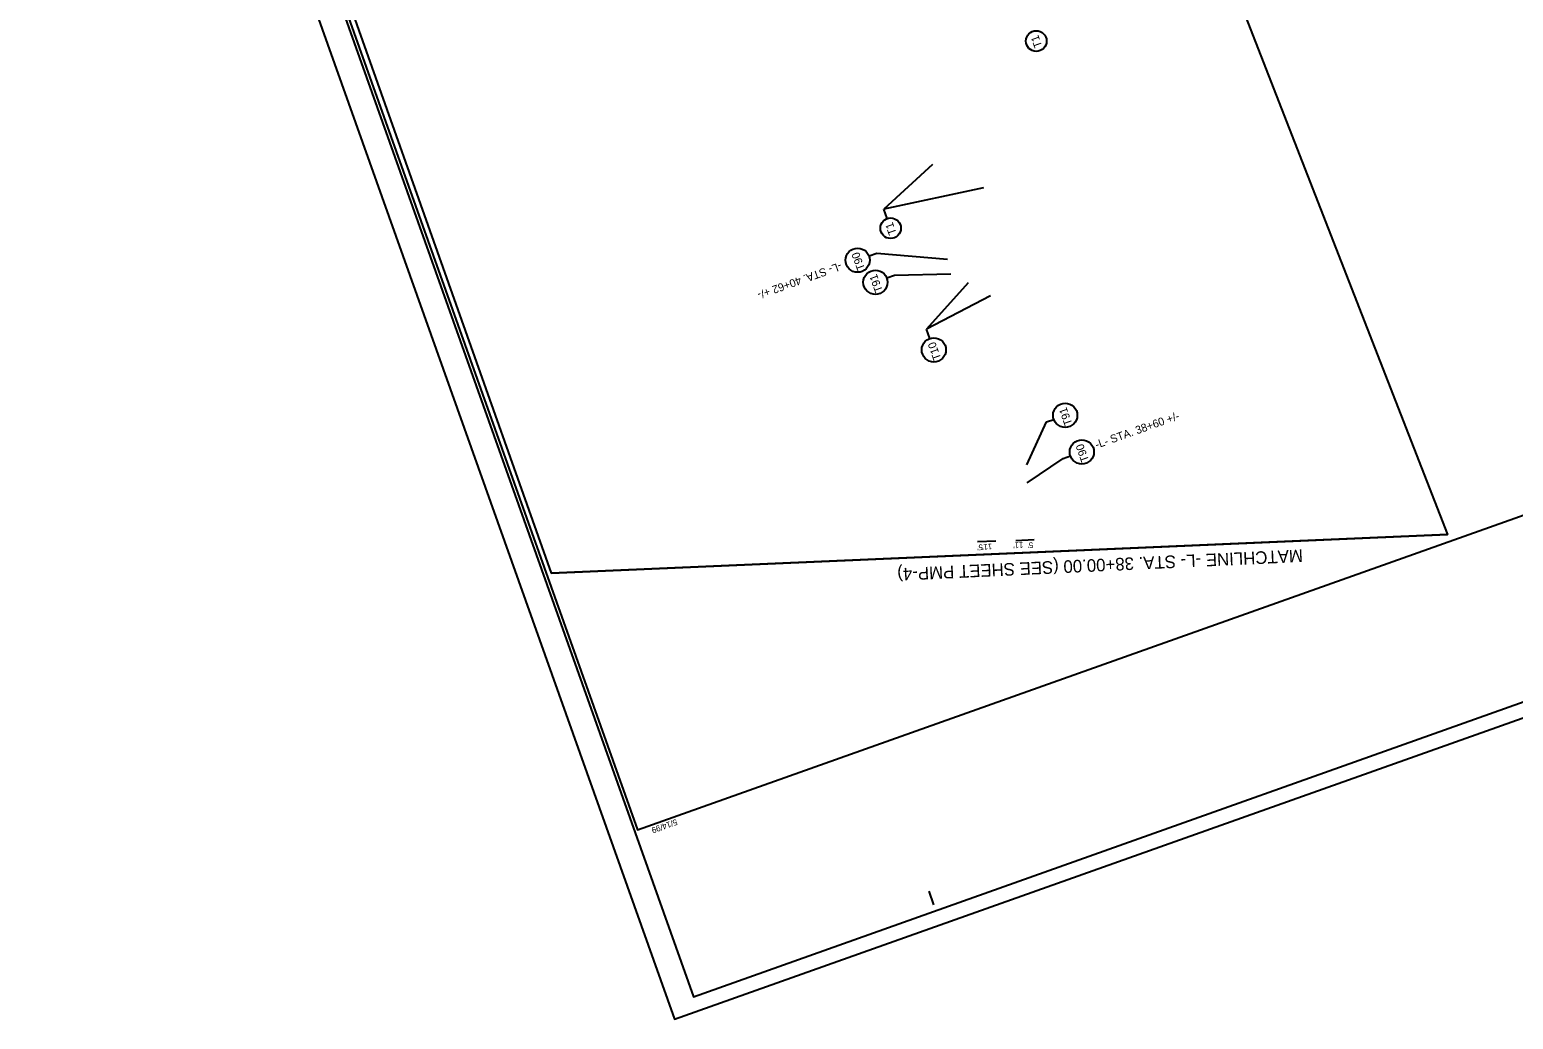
# Model space of a CAD drawing. Extents: x 1615843 to 1617934, y 901966 to 903921.
# Drawn here: x 1615843 to 1617141, y 901966 to 902832 of the extents above; entities that cross this region are included whole.
import ezdxf

# ---------------------------------------------------------------- set-up
doc = ezdxf.new("R2010")
doc.units = 0
for name, color, linetype in [('Matchline', 7, 'Continuous'), ('Matchline Text', 7, 'Continuous'), ('Sheet Border Standard 30in CELL', 7, 'Continuous'), ('Sheet Clip Boundary CELL', 7, 'Continuous'), ('Sheet Plot Border Inside CELL', 7, 'Continuous'), ('Sheet Plot Border Outside CELL', 7, 'Continuous'), ('Sheet Sticker Incomplete CELL', 7, 'Continuous')]:
    doc.layers.add(name, color=color, linetype=linetype)

msp = doc.modelspace()

# ---------------------------------------------------------------- linework, layer by layer
at = {"layer": 'Matchline'}
msp.add_line((1616299.5, 902356.1), (1617083.5, 902390), dxfattribs=at)
at = {"layer": 'Sheet Border Standard 30in CELL'}
for p, q in [((1616374.4, 902132.3), (1616374.4, 902132.3)), ((1616634.1, 902066), (1616629.9, 902077.8))]:
    msp.add_line(p, q, dxfattribs=at)
msp.add_lwpolyline([(1615872.3, 903544.7), (1616374.7, 902131.4), (1617364.1, 902483.1), (1616861.6, 903896.5)], close=True, dxfattribs=at)
at = {"layer": 'Sheet Clip Boundary CELL'}
for p, q in [((1616632.8, 902714), (1616590.3, 902674.8)), ((1616677.6, 902693.3), (1616590.3, 902674.8)), ((1616593.2, 902666.6), (1616590.3, 902674.8)), ((1616584.2, 902636.1), (1616577.4, 902633.6)), ((1616646.1, 902630.7), (1616584.2, 902636.1)), ((1616599.8, 902616.8), (1616593, 902614.4)), ((1616649.1, 902617.8), (1616599.8, 902616.8)), ((1616664.1, 902610.4), (1616627.7, 902569.7)), ((1616683.7, 902598.8), (1616627.7, 902569.7)), ((1616683.7, 902598.8), (1616627.7, 902569.7)), ((1616630.6, 902561.5), (1616627.7, 902569.7)), ((1616715.4, 902451.1), (1616732.8, 902488.6)), ((1616732.8, 902488.6), (1616739, 902490.8)), ((1616715.7, 902435.1), (1616747.3, 902456.5)), ((1616747.3, 902456.5), (1616753.6, 902458.8)), ((1616705.9, 902384.9), (1616721.9, 902385.5)), ((1616688.4, 902384.2), (1616672.4, 902383.5))]:
    msp.add_line(p, q, dxfattribs=at)
for centre, radius in [((1616723.7, 902821.9), 9.01), ((1616596.3, 902658.1), 9.01), ((1616567.4, 902630.1), 10.6), ((1616583, 902610.8), 10.6), ((1616634.1, 902551.6), 10.6), ((1616749, 902494.4), 10.6), ((1616763.6, 902462.3), 10.6)]:
    msp.add_circle(centre, radius, dxfattribs=at)
at = {"layer": 'Sheet Plot Border Inside CELL'}
msp.add_lwpolyline([(1615865.7, 903555.7), (1616423.9, 901985.4), (1617418.1, 902338.9), (1616859.8, 903909.1)], close=True, dxfattribs=at)
at = {"layer": 'Sheet Plot Border Outside CELL'}
msp.add_lwpolyline([(1615843, 903552.4), (1616407.1, 901965.7), (1617443.6, 902334.1), (1616879.5, 903920.8)], close=True, dxfattribs=at)
at = {"layer": 'Sheet Sticker Incomplete CELL'}
msp.add_lwpolyline([(1616920.6, 902383), (1616299.5, 902356.1), (1615953.1, 903334.3), (1616369.2, 903520.6), (1616903.3, 903759.8), (1617120.2, 903154.3), (1616822.6, 903060), (1617083.5, 902390)], close=True, dxfattribs=at)

# ---------------------------------------------------------------- texts
at = {"layer": 'Matchline Text'}
msp.add_text('MATCHLINE -L- STA. 38+00.00 (SEE SHEET PMP-4)', height=11, rotation=182.6625, dxfattribs=at).set_placement((1616956.7, 902377))
at = {"layer": 'Sheet Border Standard 30in CELL'}
msp.add_text('5/14/99', height=5.25, rotation=199.5707, dxfattribs=at).set_placement((1616408.6, 902141.1))
at = {"layer": 'Sheet Clip Boundary CELL'}
for s, height, rotation, p in [('T1', 7, 109.5399, (1616729, 902817.4)), ('T1', 7, 109.5399, (1616601.6, 902653.6)), ('T90', 7, 110.1663, (1616574, 902622.7)), ('-L- STA. 40+62 +/-', 7, 199.5707, (1616552, 902628.5)), ('T91', 7, 110.1663, (1616589.6, 902603.4)), ('T10', 7, 109.5707, (1616640.6, 902544)), ('T91', 7, 109.5707, (1616755.4, 902486.8)), ('-L- STA. 38+60 +/-', 7, 19.5707, (1616776.6, 902465.1)), ('T90', 7, 109.5707, (1616770, 902454.8)), ("5'", 5, 185.3744, (1616676.7, 902381.5)), ("11'", 5, 185.3744, (1616684.8, 902382.1)), ("11'", 5, 182.5285, (1616712.2, 902383.3)), ("5'", 5, 182.5285, (1616720.8, 902383.3))]:
    msp.add_text(s, height=height, rotation=rotation, dxfattribs=at).set_placement(p)

doc.saveas('drawing.dxf')
